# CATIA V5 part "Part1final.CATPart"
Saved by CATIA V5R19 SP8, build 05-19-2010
Part number: Part1
Bounding box of the stored display mesh (mm): x -29.992 to 29.992, y -100 to 117.697, z -30 to 30
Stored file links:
  D:\Dropbox\CIAO82010_JCF\SAMADI\7-SAMADI\Part1final.CATPart
  U:\lbara7\samadiprojet1mecanisme.CATProduct
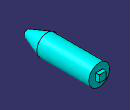
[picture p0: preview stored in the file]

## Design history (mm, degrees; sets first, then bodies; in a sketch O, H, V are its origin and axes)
Parameters
  LENGTH = 10 mm
Body1 (main body)
  Sketch1 on yz-plane, origin (0, 0, 0), H (0, 1, 0), V (0, 0, 1)
    point P1 (107.697, 0)
    line L1 (107.697, 0) -> (107.697, 30)
    line L2 (107.697, 30) -> (-42.303, 30)
    line L3 (-42.303, 30) -> (-100, 9)
    line L4 (-100, 9) -> (-100, 0)
    point P5 (-100, 0)
    axis line L5 (138.0565, 0) -> (-201.6352, 0)
    point P6 (138.0565, 0)
    length L1 = 30 {= LENGTH *3}
    length L4 = 9 {= LENGTH *0.9}
    length L2 = 150 {= LENGTH *15}
    distance L4 V = 100 {= LENGTH *10}
    angle L3 L5 = 20
    coincidence: P1 H, P5 H, P6 H
    vertical: L1 V, L4 V
    horizontal: L2 H, L5 H
  Shaft1: profile Sketch1, axis Sketch1.L5, angle 360
  Sketch2 on face of Shaft1 from Sketch1.L1, origin (0, 107.697, 0), H (-1, 0, 0), V (0, 0, 1)
    line L1 (-10, 10) -> (10, 10)
    line L2 (10, 10) -> (10, -10)
    line L3 (10, -10) -> (-10, -10)
    line L4 (-10, -10) -> (-10, 10)
    distance V L2 = 10 {= LENGTH *1}
    distance L3 H = 10 {= LENGTH *1}
    length L4 = 20 {= LENGTH *2}
    length L3 = 20 {= LENGTH *2}
    horizontal: L1 H, L3 H
    vertical: L2 V, L4 V
  Pad1: profile Sketch2, direction (0, 1, 0), length 10 {= LENGTH *1}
